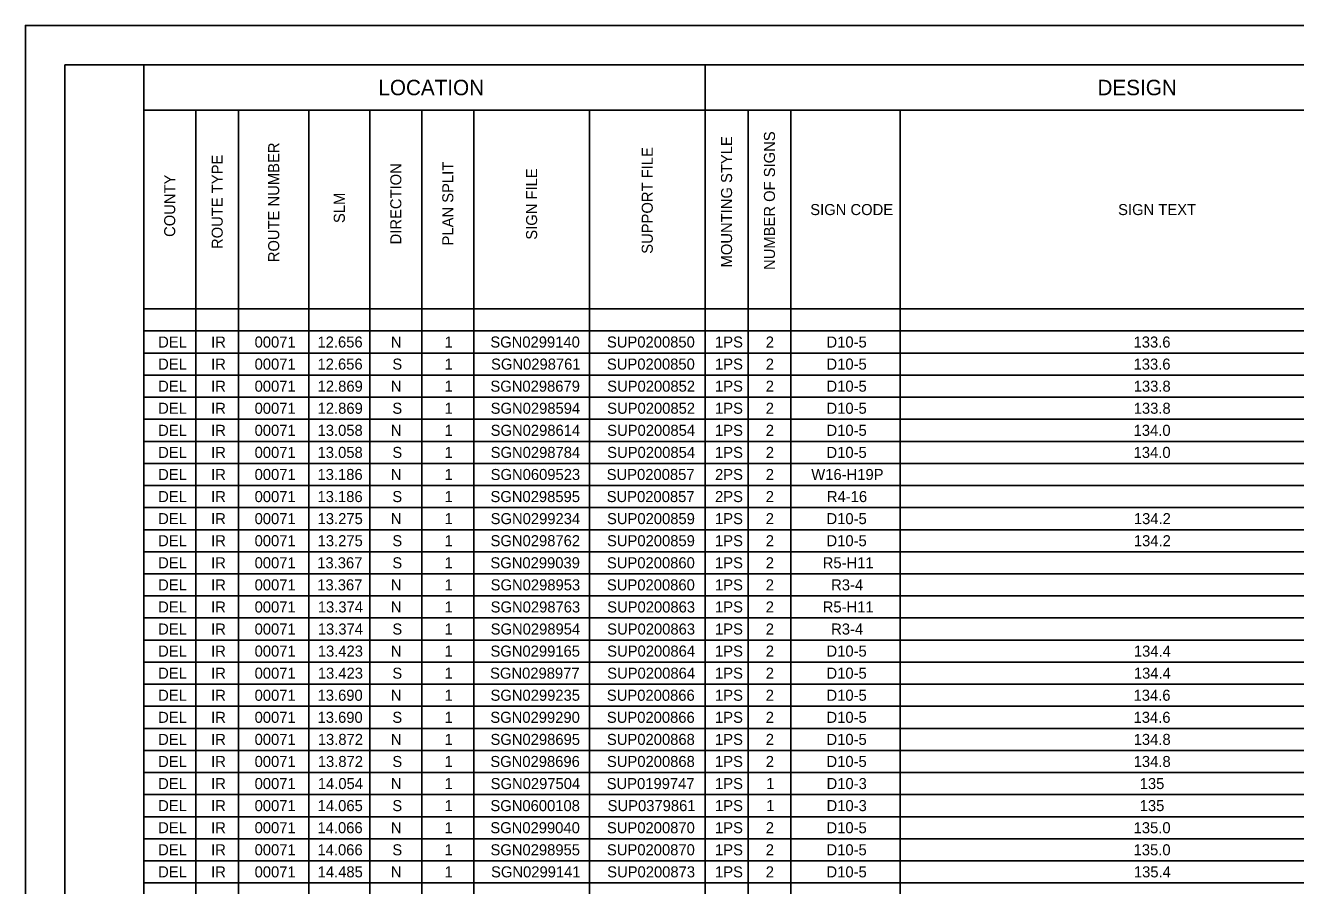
# Model space of a CAD drawing. Extents: x 0 to 34, y 0 to 22.
# Drawn here: x 0 to 16.1, y 11.09 to 22 of the extents above; entities that cross this region are included whole.
import ezdxf

# ---------------------------------------------------------------- set-up
doc = ezdxf.new("R2010")
doc.units = 0
for name, color, linetype in [('SH_Border', 7, 'Continuous'), ('SH_Cut_Line', 7, 'Continuous'), ('SH_Data', 7, 'Continuous'), ('SH_Text', 7, 'Continuous')]:
    doc.layers.add(name, color=color, linetype=linetype)

msp = doc.modelspace()

# ---------------------------------------------------------------- linework, layer by layer
at = {"layer": 'SH_Border'}
for points in [[(0.5, 21.5), (1.5, 21.5), (1.5, 0.5), (0.5, 0.5)], [(1.5, 21.5), (33.5, 21.5), (33.5, 0.5), (1.5, 0.5)]]:
    msp.add_lwpolyline(points, close=True, dxfattribs=at)
at = {"layer": 'SH_Cut_Line'}
msp.add_lwpolyline([(0, 0), (34, 0), (34, 22), (0, 22)], close=True, dxfattribs=at)
at = {"layer": 'SH_Data'}
for p, q in [((1.5, 21.5), (32.004, 21.5)), ((8.615, 21.5), (8.615, 0.764)), ((1.5, 20.924), (28.232, 20.924)), ((1.5, 20.924), (1.5, 0.764)), ((2.159, 20.924), (2.159, 0.764)), ((2.702, 20.924), (2.702, 0.764)), ((3.592, 20.924), (3.592, 0.764)), ((4.366, 20.924), (4.366, 0.764)), ((5.025, 20.924), (5.025, 0.764)), ((5.684, 20.924), (5.684, 0.764)), ((7.149, 20.924), (7.149, 0.764)), ((9.159, 20.924), (9.159, 0.764)), ((9.702, 20.924), (9.702, 0.764)), ((11.086, 20.924), (11.086, 0.764)), ((1.5, 18.404), (32.004, 18.404)), ((1.5, 18.124), (32.004, 18.124)), ((1.5, 17.844), (32.004, 17.844)), ((1.5, 17.564), (32.004, 17.564)), ((1.5, 17.284), (32.004, 17.284)), ((1.5, 17.004), (32.004, 17.004)), ((1.5, 16.724), (32.004, 16.724)), ((1.5, 16.444), (32.004, 16.444)), ((1.5, 16.164), (32.004, 16.164)), ((1.5, 15.884), (32.004, 15.884)), ((1.5, 15.604), (32.004, 15.604)), ((1.5, 15.324), (32.004, 15.324)), ((1.5, 15.044), (32.004, 15.044)), ((1.5, 14.764), (32.004, 14.764)), ((1.5, 14.484), (32.004, 14.484)), ((1.5, 14.204), (32.004, 14.204)), ((1.5, 13.924), (32.004, 13.924)), ((1.5, 13.644), (32.004, 13.644)), ((1.5, 13.364), (32.004, 13.364)), ((1.5, 13.084), (32.004, 13.084)), ((1.5, 12.804), (32.004, 12.804)), ((1.5, 12.524), (32.004, 12.524)), ((1.5, 12.244), (32.004, 12.244)), ((1.5, 11.964), (32.004, 11.964)), ((1.5, 11.684), (32.004, 11.684)), ((1.5, 11.404), (32.004, 11.404)), ((1.5, 11.124), (32.004, 11.124))]:
    msp.add_line(p, q, dxfattribs=at)

# ---------------------------------------------------------------- texts
at = {"layer": 'SH_Text'}
for s, height, p in [('LOCATION', 0.196, (4.474, 21.114)), ('DESIGN', 0.196, (13.589, 21.114)), ('SIGN CODE', 0.14, (9.948, 19.594)), ('SIGN TEXT', 0.14, (13.85, 19.594)), ('DEL', 0.14, (1.683, 17.914)), ('IR', 0.14, (2.354, 17.914)), ('00071', 0.14, (2.905, 17.914)), ('12.656', 0.14, (3.702, 17.914)), ('N', 0.14, (4.632, 17.914)), ('1', 0.14, (5.313, 17.914)), ('SGN0299140', 0.14, (5.893, 17.914)), ('SUP0200850', 0.14, (7.371, 17.914)), ('1PS', 0.14, (8.741, 17.914)), ('2', 0.14, (9.384, 17.914)), ('D10-5', 0.14, (10.154, 17.914)), ('133.6', 0.14, (14.046, 17.914)), ('DEL', 0.14, (1.683, 17.634)), ('IR', 0.14, (2.354, 17.634)), ('00071', 0.14, (2.905, 17.634)), ('12.656', 0.14, (3.702, 17.634)), ('S', 0.14, (4.651, 17.634)), ('1', 0.14, (5.313, 17.634)), ('SGN0298761', 0.14, (5.902, 17.634)), ('SUP0200850', 0.14, (7.371, 17.634)), ('1PS', 0.14, (8.741, 17.634)), ('2', 0.14, (9.384, 17.634)), ('D10-5', 0.14, (10.154, 17.634)), ('133.6', 0.14, (14.046, 17.634)), ('DEL', 0.14, (1.683, 17.354)), ('IR', 0.14, (2.354, 17.354)), ('00071', 0.14, (2.905, 17.354)), ('12.869', 0.14, (3.704, 17.354)), ('N', 0.14, (4.632, 17.354)), ('1', 0.14, (5.313, 17.354)), ('SGN0298679', 0.14, (5.894, 17.354)), ('SUP0200852', 0.14, (7.374, 17.354)), ('1PS', 0.14, (8.741, 17.354)), ('2', 0.14, (9.384, 17.354)), ('D10-5', 0.14, (10.154, 17.354)), ('133.8', 0.14, (14.048, 17.354)), ('DEL', 0.14, (1.683, 17.074)), ('IR', 0.14, (2.354, 17.074)), ('00071', 0.14, (2.905, 17.074)), ('12.869', 0.14, (3.704, 17.074)), ('S', 0.14, (4.651, 17.074)), ('1', 0.14, (5.313, 17.074)), ('SGN0298594', 0.14, (5.897, 17.074)), ('SUP0200852', 0.14, (7.374, 17.074)), ('1PS', 0.14, (8.741, 17.074)), ('2', 0.14, (9.384, 17.074)), ('D10-5', 0.14, (10.154, 17.074)), ('133.8', 0.14, (14.048, 17.074)), ('DEL', 0.14, (1.683, 16.794)), ('IR', 0.14, (2.354, 16.794)), ('00071', 0.14, (2.905, 16.794)), ('13.058', 0.14, (3.703, 16.794)), ('N', 0.14, (4.632, 16.794)), ('1', 0.14, (5.313, 16.794)), ('SGN0298614', 0.14, (5.897, 16.794)), ('SUP0200854', 0.14, (7.374, 16.794)), ('1PS', 0.14, (8.741, 16.794)), ('2', 0.14, (9.384, 16.794)), ('D10-5', 0.14, (10.154, 16.794)), ('134.0', 0.14, (14.047, 16.794)), ('DEL', 0.14, (1.683, 16.514)), ('IR', 0.14, (2.354, 16.514)), ('00071', 0.14, (2.905, 16.514)), ('13.058', 0.14, (3.703, 16.514)), ('S', 0.14, (4.651, 16.514)), ('1', 0.14, (5.313, 16.514)), ('SGN0298784', 0.14, (5.897, 16.514)), ('SUP0200854', 0.14, (7.374, 16.514)), ('1PS', 0.14, (8.741, 16.514)), ('2', 0.14, (9.384, 16.514)), ('D10-5', 0.14, (10.154, 16.514)), ('134.0', 0.14, (14.047, 16.514)), ('DEL', 0.14, (1.683, 16.234)), ('IR', 0.14, (2.354, 16.234)), ('00071', 0.14, (2.905, 16.234)), ('13.186', 0.14, (3.702, 16.234)), ('N', 0.14, (4.632, 16.234)), ('1', 0.14, (5.313, 16.234)), ('SGN0609523', 0.14, (5.897, 16.234)), ('SUP0200857', 0.14, (7.368, 16.234)), ('2PS', 0.14, (8.741, 16.234)), ('2', 0.14, (9.384, 16.234)), ('W16-H19P', 0.14, (9.961, 16.234)), ('DEL', 0.14, (1.683, 15.954)), ('IR', 0.14, (2.354, 15.954)), ('00071', 0.14, (2.905, 15.954)), ('13.186', 0.14, (3.702, 15.954)), ('S', 0.14, (4.651, 15.954)), ('1', 0.14, (5.313, 15.954)), ('SGN0298595', 0.14, (5.895, 15.954)), ('SUP0200857', 0.14, (7.368, 15.954)), ('2PS', 0.14, (8.741, 15.954)), ('2', 0.14, (9.384, 15.954)), ('R4-16', 0.14, (10.159, 15.954)), ('DEL', 0.14, (1.683, 15.674)), ('IR', 0.14, (2.354, 15.674)), ('00071', 0.14, (2.905, 15.674)), ('13.275', 0.14, (3.704, 15.674)), ('N', 0.14, (4.632, 15.674)), ('1', 0.14, (5.313, 15.674)), ('SGN0299234', 0.14, (5.897, 15.674)), ('SUP0200859', 0.14, (7.372, 15.674)), ('1PS', 0.14, (8.741, 15.674)), ('2', 0.14, (9.384, 15.674)), ('D10-5', 0.14, (10.154, 15.674)), ('134.2', 0.14, (14.05, 15.674)), ('DEL', 0.14, (1.683, 15.394)), ('IR', 0.14, (2.354, 15.394)), ('00071', 0.14, (2.905, 15.394)), ('13.275', 0.14, (3.704, 15.394)), ('S', 0.14, (4.651, 15.394)), ('1', 0.14, (5.313, 15.394)), ('SGN0298762', 0.14, (5.896, 15.394)), ('SUP0200859', 0.14, (7.372, 15.394)), ('1PS', 0.14, (8.741, 15.394)), ('2', 0.14, (9.384, 15.394)), ('D10-5', 0.14, (10.154, 15.394)), ('134.2', 0.14, (14.05, 15.394)), ('DEL', 0.14, (1.683, 15.114)), ('IR', 0.14, (2.354, 15.114)), ('00071', 0.14, (2.905, 15.114)), ('13.367', 0.14, (3.699, 15.114)), ('S', 0.14, (4.651, 15.114)), ('1', 0.14, (5.313, 15.114)), ('SGN0299039', 0.14, (5.894, 15.114)), ('SUP0200860', 0.14, (7.371, 15.114)), ('1PS', 0.14, (8.741, 15.114)), ('2', 0.14, (9.384, 15.114)), ('R5-H11', 0.14, (10.106, 15.114)), ('DEL', 0.14, (1.683, 14.834)), ('IR', 0.14, (2.354, 14.834)), ('00071', 0.14, (2.905, 14.834)), ('13.367', 0.14, (3.699, 14.834)), ('N', 0.14, (4.632, 14.834)), ('1', 0.14, (5.313, 14.834)), ('SGN0298953', 0.14, (5.897, 14.834)), ('SUP0200860', 0.14, (7.371, 14.834)), ('1PS', 0.14, (8.741, 14.834)), ('2', 0.14, (9.384, 14.834)), ('R3-4', 0.14, (10.213, 14.834)), ('DEL', 0.14, (1.683, 14.554)), ('IR', 0.14, (2.354, 14.554)), ('00071', 0.14, (2.905, 14.554)), ('13.374', 0.14, (3.706, 14.554)), ('N', 0.14, (4.632, 14.554)), ('1', 0.14, (5.313, 14.554)), ('SGN0298763', 0.14, (5.897, 14.554)), ('SUP0200863', 0.14, (7.374, 14.554)), ('1PS', 0.14, (8.741, 14.554)), ('2', 0.14, (9.384, 14.554)), ('R5-H11', 0.14, (10.106, 14.554)), ('DEL', 0.14, (1.683, 14.274)), ('IR', 0.14, (2.354, 14.274)), ('00071', 0.14, (2.905, 14.274)), ('13.374', 0.14, (3.706, 14.274)), ('S', 0.14, (4.651, 14.274)), ('1', 0.14, (5.313, 14.274)), ('SGN0298954', 0.14, (5.897, 14.274)), ('SUP0200863', 0.14, (7.374, 14.274)), ('1PS', 0.14, (8.741, 14.274)), ('2', 0.14, (9.384, 14.274)), ('R3-4', 0.14, (10.213, 14.274)), ('DEL', 0.14, (1.683, 13.994)), ('IR', 0.14, (2.354, 13.994)), ('00071', 0.14, (2.905, 13.994)), ('13.423', 0.14, (3.706, 13.994)), ('N', 0.14, (4.632, 13.994)), ('1', 0.14, (5.313, 13.994)), ('SGN0299165', 0.14, (5.895, 13.994)), ('SUP0200864', 0.14, (7.374, 13.994)), ('1PS', 0.14, (8.741, 13.994)), ('2', 0.14, (9.384, 13.994)), ('D10-5', 0.14, (10.154, 13.994)), ('134.4', 0.14, (14.05, 13.994)), ('DEL', 0.14, (1.683, 13.714)), ('IR', 0.14, (2.354, 13.714)), ('00071', 0.14, (2.905, 13.714)), ('13.423', 0.14, (3.706, 13.714)), ('S', 0.14, (4.651, 13.714)), ('1', 0.14, (5.313, 13.714)), ('SGN0298977', 0.14, (5.89, 13.714)), ('SUP0200864', 0.14, (7.374, 13.714)), ('1PS', 0.14, (8.741, 13.714)), ('2', 0.14, (9.384, 13.714)), ('D10-5', 0.14, (10.154, 13.714)), ('134.4', 0.14, (14.05, 13.714)), ('DEL', 0.14, (1.683, 13.434)), ('IR', 0.14, (2.354, 13.434)), ('00071', 0.14, (2.905, 13.434)), ('13.690', 0.14, (3.703, 13.434)), ('N', 0.14, (4.632, 13.434)), ('1', 0.14, (5.313, 13.434)), ('SGN0299235', 0.14, (5.895, 13.434)), ('SUP0200866', 0.14, (7.37, 13.434)), ('1PS', 0.14, (8.741, 13.434)), ('2', 0.14, (9.384, 13.434)), ('D10-5', 0.14, (10.154, 13.434)), ('134.6', 0.14, (14.046, 13.434)), ('DEL', 0.14, (1.683, 13.154)), ('IR', 0.14, (2.354, 13.154)), ('00071', 0.14, (2.905, 13.154)), ('13.690', 0.14, (3.703, 13.154)), ('S', 0.14, (4.651, 13.154)), ('1', 0.14, (5.313, 13.154)), ('SGN0299290', 0.14, (5.893, 13.154)), ('SUP0200866', 0.14, (7.37, 13.154)), ('1PS', 0.14, (8.741, 13.154)), ('2', 0.14, (9.384, 13.154)), ('D10-5', 0.14, (10.154, 13.154)), ('134.6', 0.14, (14.046, 13.154)), ('DEL', 0.14, (1.683, 12.874)), ('IR', 0.14, (2.354, 12.874)), ('00071', 0.14, (2.905, 12.874)), ('13.872', 0.14, (3.706, 12.874)), ('N', 0.14, (4.632, 12.874)), ('1', 0.14, (5.313, 12.874)), ('SGN0298695', 0.14, (5.895, 12.874)), ('SUP0200868', 0.14, (7.371, 12.874)), ('1PS', 0.14, (8.741, 12.874)), ('2', 0.14, (9.384, 12.874)), ('D10-5', 0.14, (10.154, 12.874)), ('134.8', 0.14, (14.048, 12.874)), ('DEL', 0.14, (1.683, 12.594)), ('IR', 0.14, (2.354, 12.594)), ('00071', 0.14, (2.905, 12.594)), ('13.872', 0.14, (3.706, 12.594)), ('S', 0.14, (4.651, 12.594)), ('1', 0.14, (5.313, 12.594)), ('SGN0298696', 0.14, (5.893, 12.594)), ('SUP0200868', 0.14, (7.371, 12.594)), ('1PS', 0.14, (8.741, 12.594)), ('2', 0.14, (9.384, 12.594)), ('D10-5', 0.14, (10.154, 12.594)), ('134.8', 0.14, (14.048, 12.594)), ('DEL', 0.14, (1.683, 12.314)), ('IR', 0.14, (2.354, 12.314)), ('00071', 0.14, (2.905, 12.314)), ('14.054', 0.14, (3.706, 12.314)), ('N', 0.14, (4.632, 12.314)), ('1', 0.14, (5.313, 12.314)), ('SGN0297504', 0.14, (5.897, 12.314)), ('SUP0199747', 0.14, (7.368, 12.314)), ('1PS', 0.14, (8.741, 12.314)), ('1', 0.14, (9.389, 12.314)), ('D10-3', 0.14, (10.155, 12.314)), ('135', 0.14, (14.124, 12.314)), ('DEL', 0.14, (1.683, 12.034)), ('IR', 0.14, (2.354, 12.034)), ('00071', 0.14, (2.905, 12.034)), ('14.065', 0.14, (3.704, 12.034)), ('S', 0.14, (4.651, 12.034)), ('1', 0.14, (5.313, 12.034)), ('SGN0600108', 0.14, (5.894, 12.034)), ('SUP0379861', 0.14, (7.38, 12.034)), ('1PS', 0.14, (8.741, 12.034)), ('1', 0.14, (9.389, 12.034)), ('D10-3', 0.14, (10.155, 12.034)), ('135', 0.14, (14.124, 12.034)), ('DEL', 0.14, (1.683, 11.754)), ('IR', 0.14, (2.354, 11.754)), ('00071', 0.14, (2.905, 11.754)), ('14.066', 0.14, (3.702, 11.754)), ('N', 0.14, (4.632, 11.754)), ('1', 0.14, (5.313, 11.754)), ('SGN0299040', 0.14, (5.893, 11.754)), ('SUP0200870', 0.14, (7.371, 11.754)), ('1PS', 0.14, (8.741, 11.754)), ('2', 0.14, (9.384, 11.754)), ('D10-5', 0.14, (10.154, 11.754)), ('135.0', 0.14, (14.047, 11.754)), ('DEL', 0.14, (1.683, 11.474)), ('IR', 0.14, (2.354, 11.474)), ('00071', 0.14, (2.905, 11.474)), ('14.066', 0.14, (3.702, 11.474)), ('S', 0.14, (4.651, 11.474)), ('1', 0.14, (5.313, 11.474)), ('SGN0298955', 0.14, (5.895, 11.474)), ('SUP0200870', 0.14, (7.371, 11.474)), ('1PS', 0.14, (8.741, 11.474)), ('2', 0.14, (9.384, 11.474)), ('D10-5', 0.14, (10.154, 11.474)), ('135.0', 0.14, (14.047, 11.474)), ('DEL', 0.14, (1.683, 11.194)), ('IR', 0.14, (2.354, 11.194)), ('00071', 0.14, (2.905, 11.194)), ('14.485', 0.14, (3.704, 11.194)), ('N', 0.14, (4.632, 11.194)), ('1', 0.14, (5.313, 11.194)), ('SGN0299141', 0.14, (5.902, 11.194)), ('SUP0200873', 0.14, (7.374, 11.194)), ('1PS', 0.14, (8.741, 11.194)), ('2', 0.14, (9.384, 11.194)), ('D10-5', 0.14, (10.154, 11.194)), ('135.4', 0.14, (14.05, 11.194))]:
    msp.add_text(s, height=height, dxfattribs=at).set_placement(p)
for s, p in [('NUMBER OF SIGNS', (9.501, 18.898)), ('ROUTE NUMBER', (3.217, 18.996)), ('SUPPORT FILE', (7.952, 19.103)), ('MOUNTING STYLE', (8.957, 18.93)), ('ROUTE TYPE', (2.501, 19.164)), ('DIRECTION', (4.765, 19.222)), ('PLAN SPLIT', (5.424, 19.209)), ('SIGN FILE', (6.486, 19.282)), ('COUNTY', (1.899, 19.317)), ('SLM', (4.049, 19.493))]:
    msp.add_text(s, height=0.14, rotation=90, dxfattribs=at).set_placement(p)

doc.saveas('drawing.dxf')
